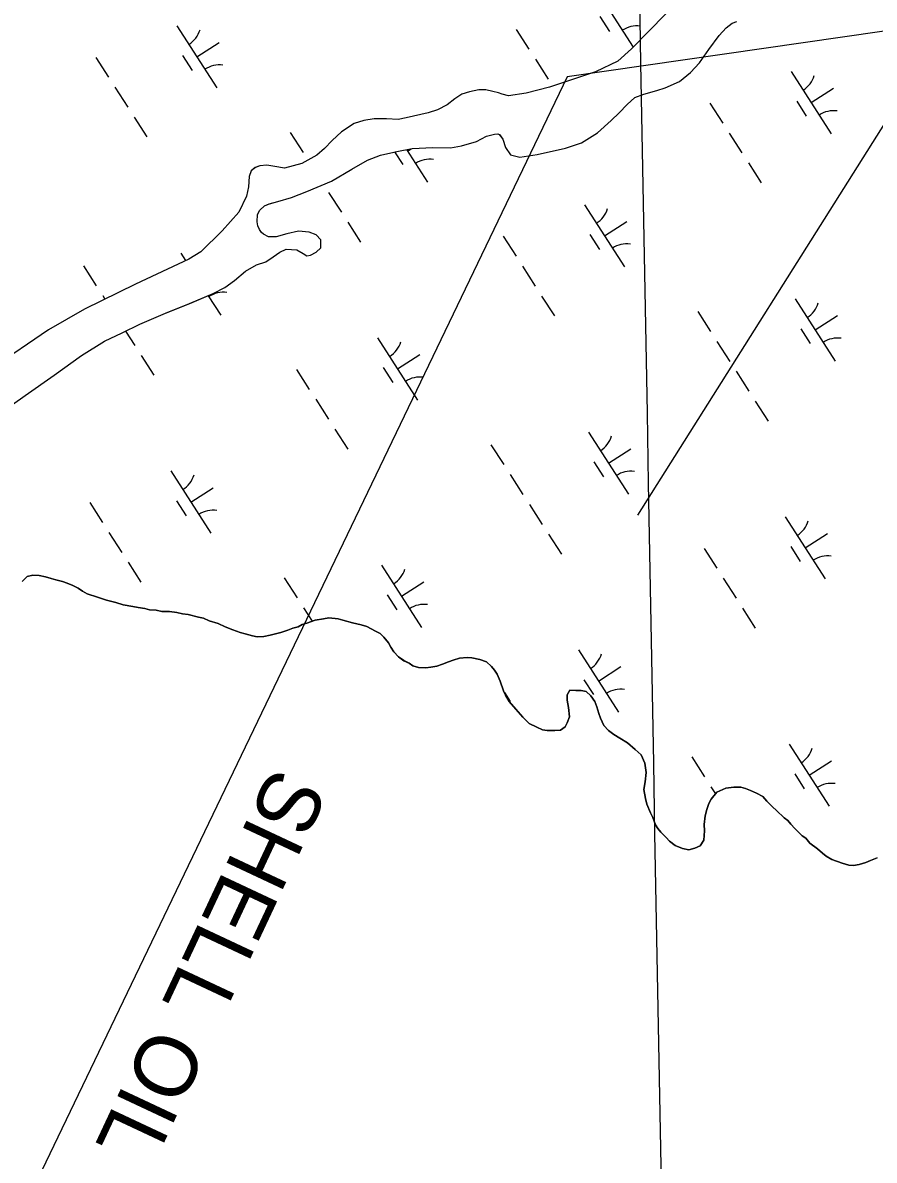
# Model space of a CAD drawing. Extents: x 3937982 to 3958556, y 219448 to 241894.
# Drawn here: x 3945563 to 3946139, y 234922 to 235692 of the extents above; entities that cross this region are included whole.
import ezdxf

# ---------------------------------------------------------------- set-up
doc = ezdxf.new("R2010")
doc.units = 0
for name, color, linetype in [('V-GRID-MAJR', 7, 'Continuous'), ('V-TOPO-SHOR', 7, 'Continuous'), ('V-UTIL-IDEN', 7, 'Continuous'), ('V-UTIL-LINE', 7, 'Continuous'), ('V-WETL-SWMP', 7, 'Continuous')]:
    doc.layers.add(name, color=color, linetype=linetype)

msp = doc.modelspace()

# ---------------------------------------------------------------- linework, layer by layer
at = {"layer": 'V-GRID-MAJR'}
msp.add_spline([(3946136.867, 227095.12), (3946078.329, 230314.506), (3945968.142, 236374.431), (3945930.73, 238431.955)], degree=3, dxfattribs=at)
at = {"layer": 'V-TOPO-SHOR'}
for points in [[(3945997.91, 235697.685), (3945974.677, 235673.853), (3945965.471, 235665.579), (3945950.333, 235658.431), (3945919.232, 235647.999), (3945903.435, 235644.009), (3945891.516, 235642.244), (3945887.158, 235643.352)], [(3945734.213, 235546.893), (3945729.138, 235546.787), (3945725.665, 235548.581), (3945724.28, 235549.824), (3945722.906, 235551.765), (3945721.89, 235554.229), (3945721.403, 235557.035), (3945721.643, 235561.929), (3945723.256, 235564.881), (3945726.269, 235567.815), (3945729.609, 235569.169), (3945735.403, 235570.668), (3945744.709, 235573.345), (3945754.912, 235577.582), (3945771.622, 235584.531), (3945785.374, 235592.572), (3945795.948, 235598.554), (3945804.918, 235602.109), (3945815.795, 235604.587), (3945826.318, 235606.547), (3945840.322, 235607.237), (3945852.213, 235606.904), (3945859.58, 235608.38), (3945869.764, 235611.395), (3945876.633, 235614.803), (3945881.901, 235616.308), (3945884.176, 235616.451), (3945885.218, 235615.913), (3945887.629, 235612.906), (3945889.478, 235607.284), (3945892.737, 235602.343), (3945899.012, 235600.686), (3945910.757, 235602.453), (3945929.879, 235606.75), (3945940.775, 235610.453), (3945951.535, 235617.133), (3945960.915, 235625.405), (3945966.233, 235630.757), (3945971.73, 235636.282), (3945976.864, 235640.937), (3945983.019, 235643.305), (3945991.798, 235645.811), (3945997.42, 235647.663), (3946007.099, 235651.906), (3946014.525, 235657.931), (3946020.561, 235664.497), (3946026.977, 235673.511), (3946033.924, 235682.864), (3946038.716, 235688.047), (3946042.781, 235691.318), (3946045.943, 235692.326)], [(3945887.158, 235643.352), (3945884.719, 235644.083), (3945880.885, 235645.185), (3945876.177, 235646.297), (3945871.276, 235646.186), (3945864.962, 235644.869), (3945859.866, 235643.188), (3945855.103, 235640.104), (3945849.976, 235636.147), (3945843.284, 235632.737), (3945836.959, 235630.722), (3945822.22, 235627.244), (3945816.782, 235626.267), (3945808.914, 235626.546), (3945800.519, 235626.656), (3945793.509, 235625.526), (3945787.009, 235623.513), (3945778.362, 235617.854), (3945772.163, 235611.989), (3945767.018, 235606.635), (3945761.708, 235601.982), (3945751.486, 235596.344), (3945739.901, 235593.176), (3945733.267, 235594.312), (3945727.856, 235595.259), (3945723.127, 235594.796), (3945720.137, 235593.612), (3945717.309, 235591.376), (3945716.037, 235587.718), (3945715.417, 235580.554), (3945714.108, 235574.275), (3945708.894, 235563.498), (3945697.706, 235550.876), (3945683.173, 235536.725), (3945675.061, 235531.758), (3945638.973, 235514.744), (3945604.638, 235497.88), (3945580.312, 235483.86), (3945542.363, 235458.299)], [(3945555.855, 235433.454), (3945564.506, 235439.461), (3945584.107, 235453.371), (3945602.476, 235466.597), (3945618.174, 235476.36), (3945630.142, 235481.973), (3945641.941, 235487.765), (3945659.357, 235495.232), (3945675.71, 235501.663), (3945691.719, 235508.448), (3945699.471, 235512.544), (3945706.006, 235517.355), (3945713.436, 235523.554), (3945721.018, 235528), (3945727.166, 235530.017), (3945732.282, 235533.274), (3945736.7, 235536.538), (3945741.099, 235538.404), (3945748.265, 235537.96), (3945752.43, 235535.631), (3945755.033, 235534.021), (3945757.487, 235534.339), (3945761.364, 235536.387), (3945764.378, 235539.496), (3945764.448, 235544.743), (3945761.343, 235548.107), (3945756.473, 235550.096), (3945749.307, 235550.717), (3945741.412, 235548.898), (3945734.213, 235546.893)], [(3945562.31, 235313.718), (3945565.855, 235317.169), (3945569.716, 235318.166), (3945573.908, 235317.763), (3945578.098, 235317.005), (3945581.932, 235315.905), (3945585.066, 235314.816), (3945589.6, 235313.706), (3945592.733, 235312.614), (3945596.563, 235311.164), (3945600.387, 235309.364), (3945603.158, 235307.228), (3945606.283, 235305.438), (3945613.25, 235303.247), (3945619.519, 235301.063), (3945625.796, 235299.581), (3945630.677, 235298.116), (3945637.308, 235296.98), (3945640.798, 235296.232), (3945645.334, 235295.472), (3945648.474, 235294.733), (3945653.016, 235294.321), (3945656.854, 235293.572), (3945662.101, 235293.502), (3945666.99, 235292.736), (3945670.83, 235291.987), (3945674.672, 235291.585), (3945681.645, 235289.744), (3945685.133, 235288.999), (3945688.959, 235287.198), (3945694.881, 235285.37), (3945699.752, 235283.207), (3945704.97, 235281.038), (3945709.844, 235279.224), (3945713.334, 235278.478), (3945718.21, 235277.014), (3945721.35, 235276.272), (3945725.902, 235276.561), (3945730.113, 235277.556), (3945737.484, 235279.207), (3945742.053, 235280.897), (3945745.569, 235282.248), (3945749.082, 235283.252), (3945751.9, 235284.614), (3945755.062, 235285.621), (3945760.686, 235287.647), (3945766.295, 235288.622), (3945769.803, 235289.273), (3945776.091, 235288.491), (3945779.228, 235287.749), (3945785.852, 235285.912), (3945791.78, 235284.436), (3945795.614, 235283.334), (3945801.519, 235280.106), (3945804.648, 235278.666), (3945807.065, 235276.184), (3945810.161, 235272.295), (3945811.873, 235269.473), (3945813.932, 235266.299), (3945817.032, 235262.76), (3945820.498, 235260.263), (3945824.323, 235258.465), (3945826.748, 235256.681), (3945830.582, 235255.581), (3945835.479, 235255.518), (3945838.983, 235255.821), (3945842.839, 235256.468), (3945846.706, 235257.818), (3945850.927, 235259.509)], [(3945850.927, 235259.509), (3945854.089, 235260.517), (3945858.304, 235261.861), (3945863.561, 235262.491), (3945866.705, 235262.1), (3945871.937, 235260.982), (3945876.465, 235259.522), (3945879.922, 235256.327), (3945881.989, 235253.851), (3945883.701, 235251.029), (3945885.739, 235246.453), (3945888.1, 235239.775), (3945889.462, 235236.959), (3945891.854, 235232.728), (3945896.333, 235227.421), (3945901.16, 235222.109), (3945905.301, 235217.855), (3945910.515, 235215.336), (3945914.341, 235213.538), (3945917.485, 235213.147), (3945922.732, 235213.075), (3945926.584, 235213.374), (3945929.76, 235215.432), (3945931.196, 235218.212), (3945932.65, 235222.392), (3945932.036, 235228.697), (3945931.051, 235233.608), (3945931.098, 235237.106), (3945932.888, 235240.232), (3945937.084, 235240.174), (3945940.582, 235240.129), (3945944.072, 235239.384), (3945947.183, 235236.543), (3945949.929, 235232.658), (3945951.283, 235229.142), (3945952.622, 235224.575), (3945953.63, 235221.413), (3945956.014, 235216.483), (3945959.114, 235212.944), (3945962.58, 235210.45), (3945966.745, 235207.945), (3945971.951, 235204.728), (3945977.139, 235200.109), (3945981.288, 235196.556), (3945983.664, 235190.926), (3945984.628, 235184.616), (3945983.846, 235178.329), (3945983.076, 235173.092), (3945984.047, 235167.13), (3945985.046, 235163.27), (3945987.416, 235157.29), (3945989.124, 235154.119), (3945990.807, 235149.198), (3945992.523, 235146.726), (3945994.59, 235144.25), (3945998.041, 235140.705), (3946000.457, 235138.225), (3946004.269, 235135.376), (3946009.137, 235133.211), (3946013.327, 235132.458), (3946017.538, 235133.451), (3946021.058, 235135.153), (3946023.559, 235138.968), (3946023.991, 235145.26), (3946023.696, 235149.462), (3946024.476, 235155.399), (3946025.58, 235159.583), (3946027.034, 235163.761), (3946028.472, 235166.543), (3946032.384, 235171.388), (3946038.368, 235174.108), (3946043.973, 235174.733), (3946048.522, 235174.673), (3946051.659, 235173.932), (3946055.141, 235172.486), (3946059.315, 235170.682), (3946063.485, 235168.527), (3946066.241, 235165.342), (3946070.036, 235161.443), (3946072.803, 235158.957), (3946077.984, 235153.99), (3946080.411, 235152.209), (3946082.478, 235149.733), (3946085.238, 235146.896), (3946090.072, 235141.936), (3946092.497, 235140.152), (3946095.253, 235136.967), (3946100.449, 235133.052), (3946103.91, 235130.207), (3946106.331, 235128.075), (3946110.15, 235125.925), (3946117.113, 235123.383), (3946121.644, 235121.925), (3946124.791, 235121.882), (3946128.648, 235122.531), (3946133.215, 235123.87), (3946136.381, 235125.226), (3946140.95, 235126.916)]]:
    msp.add_lwpolyline(points, dxfattribs=at)
at = {"layer": 'V-UTIL-LINE'}
msp.add_line((3947949.336, 238483.295), (3945978.591, 235358.555), dxfattribs=at)
msp.add_lwpolyline([(3948094.548, 238926.698), (3947981.77, 238738.296), (3948844.302, 237642.921), (3949260.796, 236134.673), (3945931.135, 235655.081), (3945509.058, 234777.685), (3943601.185, 231807.758)], dxfattribs=at)
at = {"layer": 'V-WETL-SWMP'}
for p, q in [((3945949.473, 235715.897), (3945975.797, 235675.001)), ((3945667.04, 235689.558), (3945694.103, 235647.515)), ((3945953.269, 235695.745), (3945959.764, 235685.655)), ((3945896.598, 235687.122), (3945905.258, 235673.668)), ((3945680.571, 235668.537), (3945695.707, 235678.279)), ((3945612.174, 235668.161), (3945620.834, 235654.707)), ((3945670.836, 235669.406), (3945677.331, 235659.315)), ((3945909.588, 235666.941), (3945918.248, 235653.487)), ((3946082.603, 235658.599), (3946109.665, 235616.556)), ((3945625.164, 235647.98), (3945633.824, 235634.527)), ((3946096.134, 235637.577), (3946111.269, 235647.32)), ((3946027.737, 235637.202), (3946036.397, 235623.748)), ((3946086.399, 235638.447), (3946092.894, 235628.356)), ((3945638.154, 235627.8), (3945646.814, 235614.346)), ((3945743.741, 235617.273), (3945752.401, 235603.819)), ((3946040.727, 235617.021), (3946049.386, 235603.567)), ((3945822.5, 235605.837), (3945836.668, 235583.825)), ((3945823.137, 235604.846), (3945825.562, 235606.407)), ((3945814.341, 235604.256), (3945819.897, 235595.625)), ((3946053.716, 235596.84), (3946062.376, 235583.387)), ((3945769.721, 235576.912), (3945778.381, 235563.458)), ((3945942.735, 235568.569), (3945969.798, 235526.526)), ((3945782.711, 235556.731), (3945791.371, 235543.277)), ((3945956.267, 235547.548), (3945971.402, 235557.29)), ((3945887.869, 235547.172), (3945896.529, 235533.718)), ((3945946.531, 235548.417), (3945953.026, 235538.327)), ((3945669.739, 235535.838), (3945672.993, 235530.784)), ((3945603.874, 235527.244), (3945612.534, 235513.79)), ((3945900.859, 235526.992), (3945909.519, 235513.538)), ((3945616.864, 235507.063), (3945618.418, 235504.648)), ((3945688.303, 235506.999), (3945696.801, 235493.795)), ((3945913.849, 235506.811), (3945922.509, 235493.357)), ((3946085.301, 235504.879), (3946112.364, 235462.836)), ((3946019.436, 235496.284), (3946028.096, 235482.83)), ((3946098.832, 235483.858), (3946113.968, 235493.6)), ((3945632.324, 235483.045), (3945638.514, 235473.428)), ((3946089.097, 235484.727), (3946095.592, 235474.636)), ((3945802.868, 235478.54), (3945829.93, 235436.497)), ((3946032.426, 235476.104), (3946041.086, 235462.65)), ((3945642.844, 235466.701), (3945651.504, 235453.247)), ((3945816.399, 235457.518), (3945831.535, 235467.261)), ((3945748.002, 235457.143), (3945756.662, 235443.689)), ((3945806.664, 235458.387), (3945813.159, 235448.297)), ((3946045.416, 235455.923), (3946054.076, 235442.469)), ((3945760.992, 235436.962), (3945769.652, 235423.508)), ((3946058.406, 235435.742), (3946067.066, 235422.288)), ((3945773.982, 235416.781), (3945782.642, 235403.328)), ((3945945.434, 235414.85), (3945972.496, 235372.807)), ((3945879.569, 235406.255), (3945888.229, 235392.801)), ((3945958.965, 235393.828), (3945974.101, 235403.571)), ((3945949.23, 235394.697), (3945955.725, 235384.607)), ((3945663.001, 235388.51), (3945690.063, 235346.467)), ((3945892.559, 235386.074), (3945901.219, 235372.62)), ((3945676.532, 235367.489), (3945691.668, 235377.231)), ((3945608.135, 235367.113), (3945616.795, 235353.659)), ((3945666.797, 235368.358), (3945673.292, 235358.268)), ((3945905.549, 235365.893), (3945914.209, 235352.439)), ((3946078.563, 235357.551), (3946105.626, 235315.508)), ((3945621.125, 235346.933), (3945629.785, 235333.479)), ((3945918.539, 235345.713), (3945927.199, 235332.259)), ((3946092.094, 235336.53), (3946107.23, 235346.272)), ((3946023.697, 235336.154), (3946032.357, 235322.7)), ((3946082.359, 235337.399), (3946088.854, 235327.308)), ((3945634.115, 235326.752), (3945642.775, 235313.298)), ((3945805.567, 235324.82), (3945832.629, 235282.777)), ((3945739.702, 235316.225), (3945748.362, 235302.771)), ((3945819.098, 235303.799), (3945834.233, 235313.541)), ((3946036.687, 235315.973), (3946045.347, 235302.519)), ((3945809.363, 235304.668), (3945815.858, 235294.577)), ((3945752.692, 235296.045), (3945758.584, 235286.89)), ((3946049.677, 235295.793), (3946058.337, 235282.339)), ((3945938.696, 235267.522), (3945965.758, 235225.478)), ((3945952.227, 235246.5), (3945967.363, 235256.242)), ((3945942.492, 235247.369), (3945948.987, 235237.279)), ((3945888.648, 235238.639), (3945892.49, 235232.671)), ((3946081.262, 235203.831), (3946108.324, 235161.788)), ((3946015.397, 235195.237), (3946024.057, 235181.783)), ((3946094.793, 235182.81), (3946109.929, 235192.552)), ((3946085.058, 235183.679), (3946091.553, 235173.589)), ((3946028.387, 235175.056), (3946031.474, 235170.26))]:
    msp.add_line(p, q, dxfattribs=at)
for points in [[(3945997.91, 235697.686), (3945974.678, 235673.853), (3945965.471, 235665.579), (3945950.333, 235658.432), (3945919.231, 235647.999), (3945903.435, 235644.01), (3945891.516, 235642.244), (3945887.157, 235643.351), (3945884.718, 235644.083), (3945880.884, 235645.184), (3945876.176, 235646.296), (3945871.276, 235646.186), (3945864.961, 235644.87), (3945859.866, 235643.188), (3945855.102, 235640.103), (3945849.976, 235636.147), (3945843.284, 235632.738), (3945836.96, 235630.722), (3945822.219, 235627.244), (3945816.783, 235626.267), (3945808.915, 235626.546), (3945800.52, 235626.657), (3945793.508, 235625.526), (3945787.009, 235623.513), (3945778.362, 235617.855), (3945772.162, 235611.989), (3945767.018, 235606.635), (3945761.708, 235601.982), (3945751.487, 235596.345), (3945739.9, 235593.175), (3945733.267, 235594.312), (3945727.857, 235595.258), (3945723.128, 235594.796), (3945720.138, 235593.612), (3945717.31, 235591.375), (3945716.037, 235587.718), (3945715.417, 235580.554), (3945714.109, 235574.274), (3945708.893, 235563.498), (3945697.705, 235550.876), (3945683.173, 235536.724), (3945675.061, 235531.759), (3945638.974, 235514.744), (3945604.639, 235497.881), (3945580.313, 235483.86), (3945542.363, 235458.298)], [(3945555.854, 235433.454), (3945564.505, 235439.462), (3945584.107, 235453.371), (3945602.475, 235466.597), (3945618.173, 235476.36), (3945630.143, 235481.974), (3945641.94, 235487.766), (3945659.357, 235495.232), (3945675.711, 235501.662), (3945691.72, 235508.447), (3945699.471, 235512.543), (3945706.007, 235517.354), (3945713.437, 235523.553), (3945721.018, 235528.001), (3945727.167, 235530.018), (3945732.283, 235533.274), (3945736.7, 235536.539), (3945741.098, 235538.405), (3945748.264, 235537.96), (3945752.431, 235535.631), (3945755.034, 235534.022), (3945757.487, 235534.339), (3945761.363, 235536.387), (3945764.378, 235539.496), (3945764.448, 235544.743), (3945761.343, 235548.108), (3945756.472, 235550.097), (3945749.308, 235550.716), (3945741.412, 235548.897), (3945734.213, 235546.893), (3945729.139, 235546.786), (3945725.664, 235548.581), (3945724.281, 235549.824), (3945722.907, 235551.766), (3945721.89, 235554.229), (3945721.403, 235557.034), (3945721.642, 235561.929), (3945723.256, 235564.881), (3945726.269, 235567.815), (3945729.61, 235569.17), (3945735.403, 235570.668), (3945744.71, 235573.344), (3945754.912, 235577.582), (3945771.623, 235584.532), (3945785.374, 235592.572), (3945795.949, 235598.554), (3945804.918, 235602.109), (3945815.796, 235604.588), (3945826.318, 235606.548), (3945840.322, 235607.237), (3945852.213, 235606.904), (3945859.579, 235608.381), (3945869.765, 235611.395), (3945876.633, 235614.802), (3945881.901, 235616.307), (3945884.177, 235616.451), (3945885.219, 235615.913), (3945887.628, 235612.907), (3945889.478, 235607.285), (3945892.736, 235602.343), (3945899.012, 235600.686), (3945910.756, 235602.454), (3945929.88, 235606.749), (3945940.775, 235610.453), (3945951.534, 235617.133), (3945960.915, 235625.405), (3945966.234, 235630.757), (3945971.73, 235636.282), (3945976.865, 235640.937), (3945983.019, 235643.305), (3945991.799, 235645.812), (3945997.421, 235647.662), (3946007.099, 235651.907), (3946014.526, 235657.931), (3946020.56, 235664.498), (3946026.977, 235673.51), (3946033.924, 235682.864), (3946038.716, 235688.048), (3946042.782, 235691.318), (3946045.944, 235692.326)], [(3945791.78, 235284.435), (3945785.852, 235285.913), (3945779.229, 235287.75), (3945776.09, 235288.491), (3945769.803, 235289.274), (3945766.296, 235288.621), (3945760.685, 235287.646), (3945755.061, 235285.622), (3945751.899, 235284.614), (3945749.082, 235283.252), (3945745.57, 235282.249), (3945742.053, 235280.896), (3945737.483, 235279.207), (3945730.114, 235277.556), (3945725.902, 235276.562), (3945721.35, 235276.272), (3945718.211, 235277.014), (3945713.333, 235278.478), (3945709.844, 235279.224), (3945704.97, 235281.038), (3945699.751, 235283.206), (3945694.881, 235285.37), (3945688.958, 235287.198), (3945685.133, 235288.998), (3945681.645, 235289.744), (3945674.672, 235291.586), (3945670.829, 235291.986), (3945666.99, 235292.737), (3945662.102, 235293.502), (3945656.855, 235293.571), (3945653.017, 235294.322), (3945648.474, 235294.732), (3945645.335, 235295.473), (3945640.797, 235296.233), (3945637.308, 235296.979), (3945630.676, 235298.117), (3945625.797, 235299.581), (3945619.52, 235301.063), (3945613.251, 235303.246), (3945606.283, 235305.437), (3945603.158, 235307.228), (3945600.387, 235309.364), (3945596.563, 235311.164), (3945592.734, 235312.614), (3945589.599, 235313.705), (3945585.066, 235314.815), (3945581.932, 235315.906), (3945578.098, 235317.006), (3945573.909, 235317.762), (3945569.716, 235318.167), (3945565.855, 235317.169), (3945562.31, 235313.717)], [(3946085.238, 235146.897), (3946082.477, 235149.732), (3946080.411, 235152.209), (3946077.985, 235153.99), (3946072.803, 235158.957), (3946070.037, 235161.443), (3946066.241, 235165.342), (3946063.484, 235168.527), (3946059.314, 235170.681), (3946055.14, 235172.486), (3946051.66, 235173.932), (3946048.522, 235174.673), (3946043.974, 235174.733), (3946038.368, 235174.108), (3946032.384, 235171.388), (3946028.472, 235166.542), (3946027.035, 235163.762), (3946025.581, 235159.583), (3946024.476, 235155.4), (3946023.697, 235149.462), (3946023.991, 235145.26), (3946023.558, 235138.968), (3946021.058, 235135.153), (3946017.537, 235133.45), (3946013.326, 235132.457), (3946009.137, 235133.212), (3946004.268, 235135.376), (3946000.457, 235138.225), (3945998.041, 235140.706), (3945994.59, 235144.251), (3945992.523, 235146.727), (3945990.807, 235149.199), (3945989.123, 235154.119), (3945987.415, 235157.29), (3945985.046, 235163.27), (3945984.047, 235167.131), (3945983.077, 235173.092), (3945983.846, 235178.329), (3945984.629, 235184.617), (3945983.663, 235190.927), (3945981.289, 235196.556), (3945977.138, 235200.11), (3945971.951, 235204.727), (3945966.746, 235207.944), (3945962.58, 235210.449), (3945959.115, 235212.944), (3945956.013, 235216.483), (3945953.63, 235221.413), (3945952.622, 235224.575), (3945951.283, 235229.141), (3945949.93, 235232.658), (3945947.183, 235236.543), (3945944.072, 235239.383), (3945940.583, 235240.129), (3945937.085, 235240.175), (3945932.887, 235240.231), (3945931.097, 235237.106), (3945931.05, 235233.608), (3945932.035, 235228.697), (3945932.651, 235222.391), (3945931.196, 235218.212), (3945929.76, 235215.432), (3945926.584, 235213.375), (3945922.731, 235213.076), (3945917.484, 235213.146), (3945914.341, 235213.537), (3945910.516, 235215.337), (3945905.302, 235217.856), (3945901.16, 235222.109), (3945896.332, 235227.421), (3945891.854, 235232.728), (3945889.461, 235236.958), (3945888.099, 235239.775), (3945885.739, 235246.454), (3945883.7, 235251.029), (3945881.988, 235253.85), (3945879.922, 235256.327), (3945876.466, 235259.521), (3945871.937, 235260.981), (3945866.704, 235262.1), (3945863.56, 235262.491), (3945858.304, 235261.861), (3945854.088, 235260.518), (3945850.926, 235259.51), (3945846.705, 235257.817), (3945842.839, 235256.469), (3945838.982, 235255.82), (3945835.479, 235255.517), (3945830.582, 235255.582), (3945826.748, 235256.682), (3945824.323, 235258.464), (3945820.498, 235260.264), (3945817.033, 235262.759), (3945813.931, 235266.298), (3945811.874, 235269.474), (3945810.162, 235272.296), (3945807.065, 235276.185), (3945804.649, 235278.666), (3945801.519, 235280.107), (3945795.614, 235283.334), (3945791.78, 235284.435)], [(3946140.951, 235126.916), (3946136.381, 235125.227), (3946133.214, 235123.87), (3946128.648, 235122.531), (3946124.791, 235121.882), (3946121.643, 235121.924), (3946117.114, 235123.384), (3946110.15, 235125.925), (3946106.33, 235128.075), (3946103.91, 235130.206), (3946100.449, 235133.051), (3946095.253, 235136.968), (3946092.496, 235140.153), (3946090.071, 235141.935), (3946085.238, 235146.897)]]:
    msp.add_lwpolyline(points, dxfattribs=at)
for centre, start, end in [((3945665.821, 235691.891), 301.99668, 343.540338), ((3945978.154, 235671.778), 81.996677, 123.540335), ((3945695.721, 235645.439), 81.996677, 123.540335), ((3946081.383, 235660.932), 301.99668, 343.540338), ((3946111.283, 235614.48), 81.996677, 123.540335), ((3945838.287, 235581.749), 81.996677, 123.540335), ((3945941.516, 235570.902), 301.99668, 343.540338), ((3945971.416, 235524.45), 81.996677, 123.540335), ((3945698.42, 235491.719), 81.996677, 123.540335), ((3946084.082, 235507.212), 301.99668, 343.540338), ((3945801.649, 235480.873), 301.99668, 343.540338), ((3946113.982, 235460.76), 81.996677, 123.540335), ((3945831.549, 235434.421), 81.996677, 123.540335), ((3945944.215, 235417.183), 301.99668, 343.540338), ((3945661.782, 235390.843), 301.99668, 343.540338), ((3945974.115, 235370.731), 81.996677, 123.540335), ((3945691.682, 235344.391), 81.996677, 123.540335), ((3946077.344, 235359.884), 301.99668, 343.540338), ((3946107.244, 235313.432), 81.996677, 123.540335), ((3945804.348, 235327.153), 301.99668, 343.540338), ((3945834.248, 235280.701), 81.996677, 123.540335), ((3945937.477, 235269.854), 301.99668, 343.540338), ((3945967.377, 235223.403), 81.996677, 123.540335), ((3946080.043, 235206.164), 301.99668, 343.540338), ((3946109.943, 235159.712), 81.996677, 123.540335)]:
    msp.add_arc(centre, 17.623, start, end, dxfattribs=at)

# ---------------------------------------------------------------- texts
at = {"layer": 'V-UTIL-IDEN'}
msp.add_text('SHELL OIL CO. ', height=41.99992, rotation=244.886309, dxfattribs=at).set_placement((3945731.93, 235190.11))

doc.saveas('drawing.dxf')
